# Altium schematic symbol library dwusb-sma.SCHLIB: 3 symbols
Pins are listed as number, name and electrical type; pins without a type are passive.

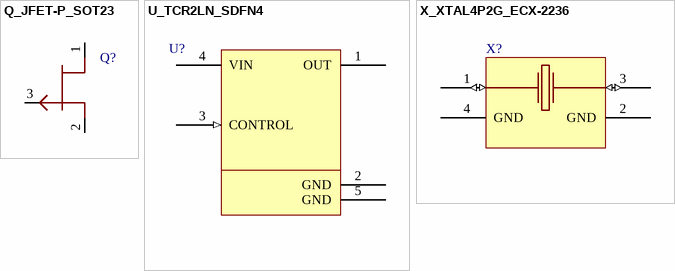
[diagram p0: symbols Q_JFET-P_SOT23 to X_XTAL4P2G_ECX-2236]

## Q_JFET-P_SOT23
designator Q?  (value not drawn)
footprint SOT23
pins: 1 D, 2 S, 3 G

## U_TCR2LN_SDFN4
designator U?  (value not drawn)
footprint SDFN4
pins: 1 OUT (power), 2 GND (power), 3 CONTROL (in), 4 VIN (power), 5 GND (power)

## X_XTAL4P2G_ECX-2236
designator X?  (value not drawn)
footprint ECX-2236
footprint 7Z-2M0X1M6-4P
pins: 1 X1 (io), 2 GND (power), 3 X2 (io), 4 GND (power)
